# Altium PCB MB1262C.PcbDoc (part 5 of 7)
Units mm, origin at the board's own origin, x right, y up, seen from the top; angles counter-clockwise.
Board outline 208 x 250 mm, 6 copper layers (Top Layer, Layer 2, Layer 3, Layer 4, Layer 5, Bottom Layer), stack 1.596 mm thick; 483 components, 502 nets, 2134 pads, 1709 vias.
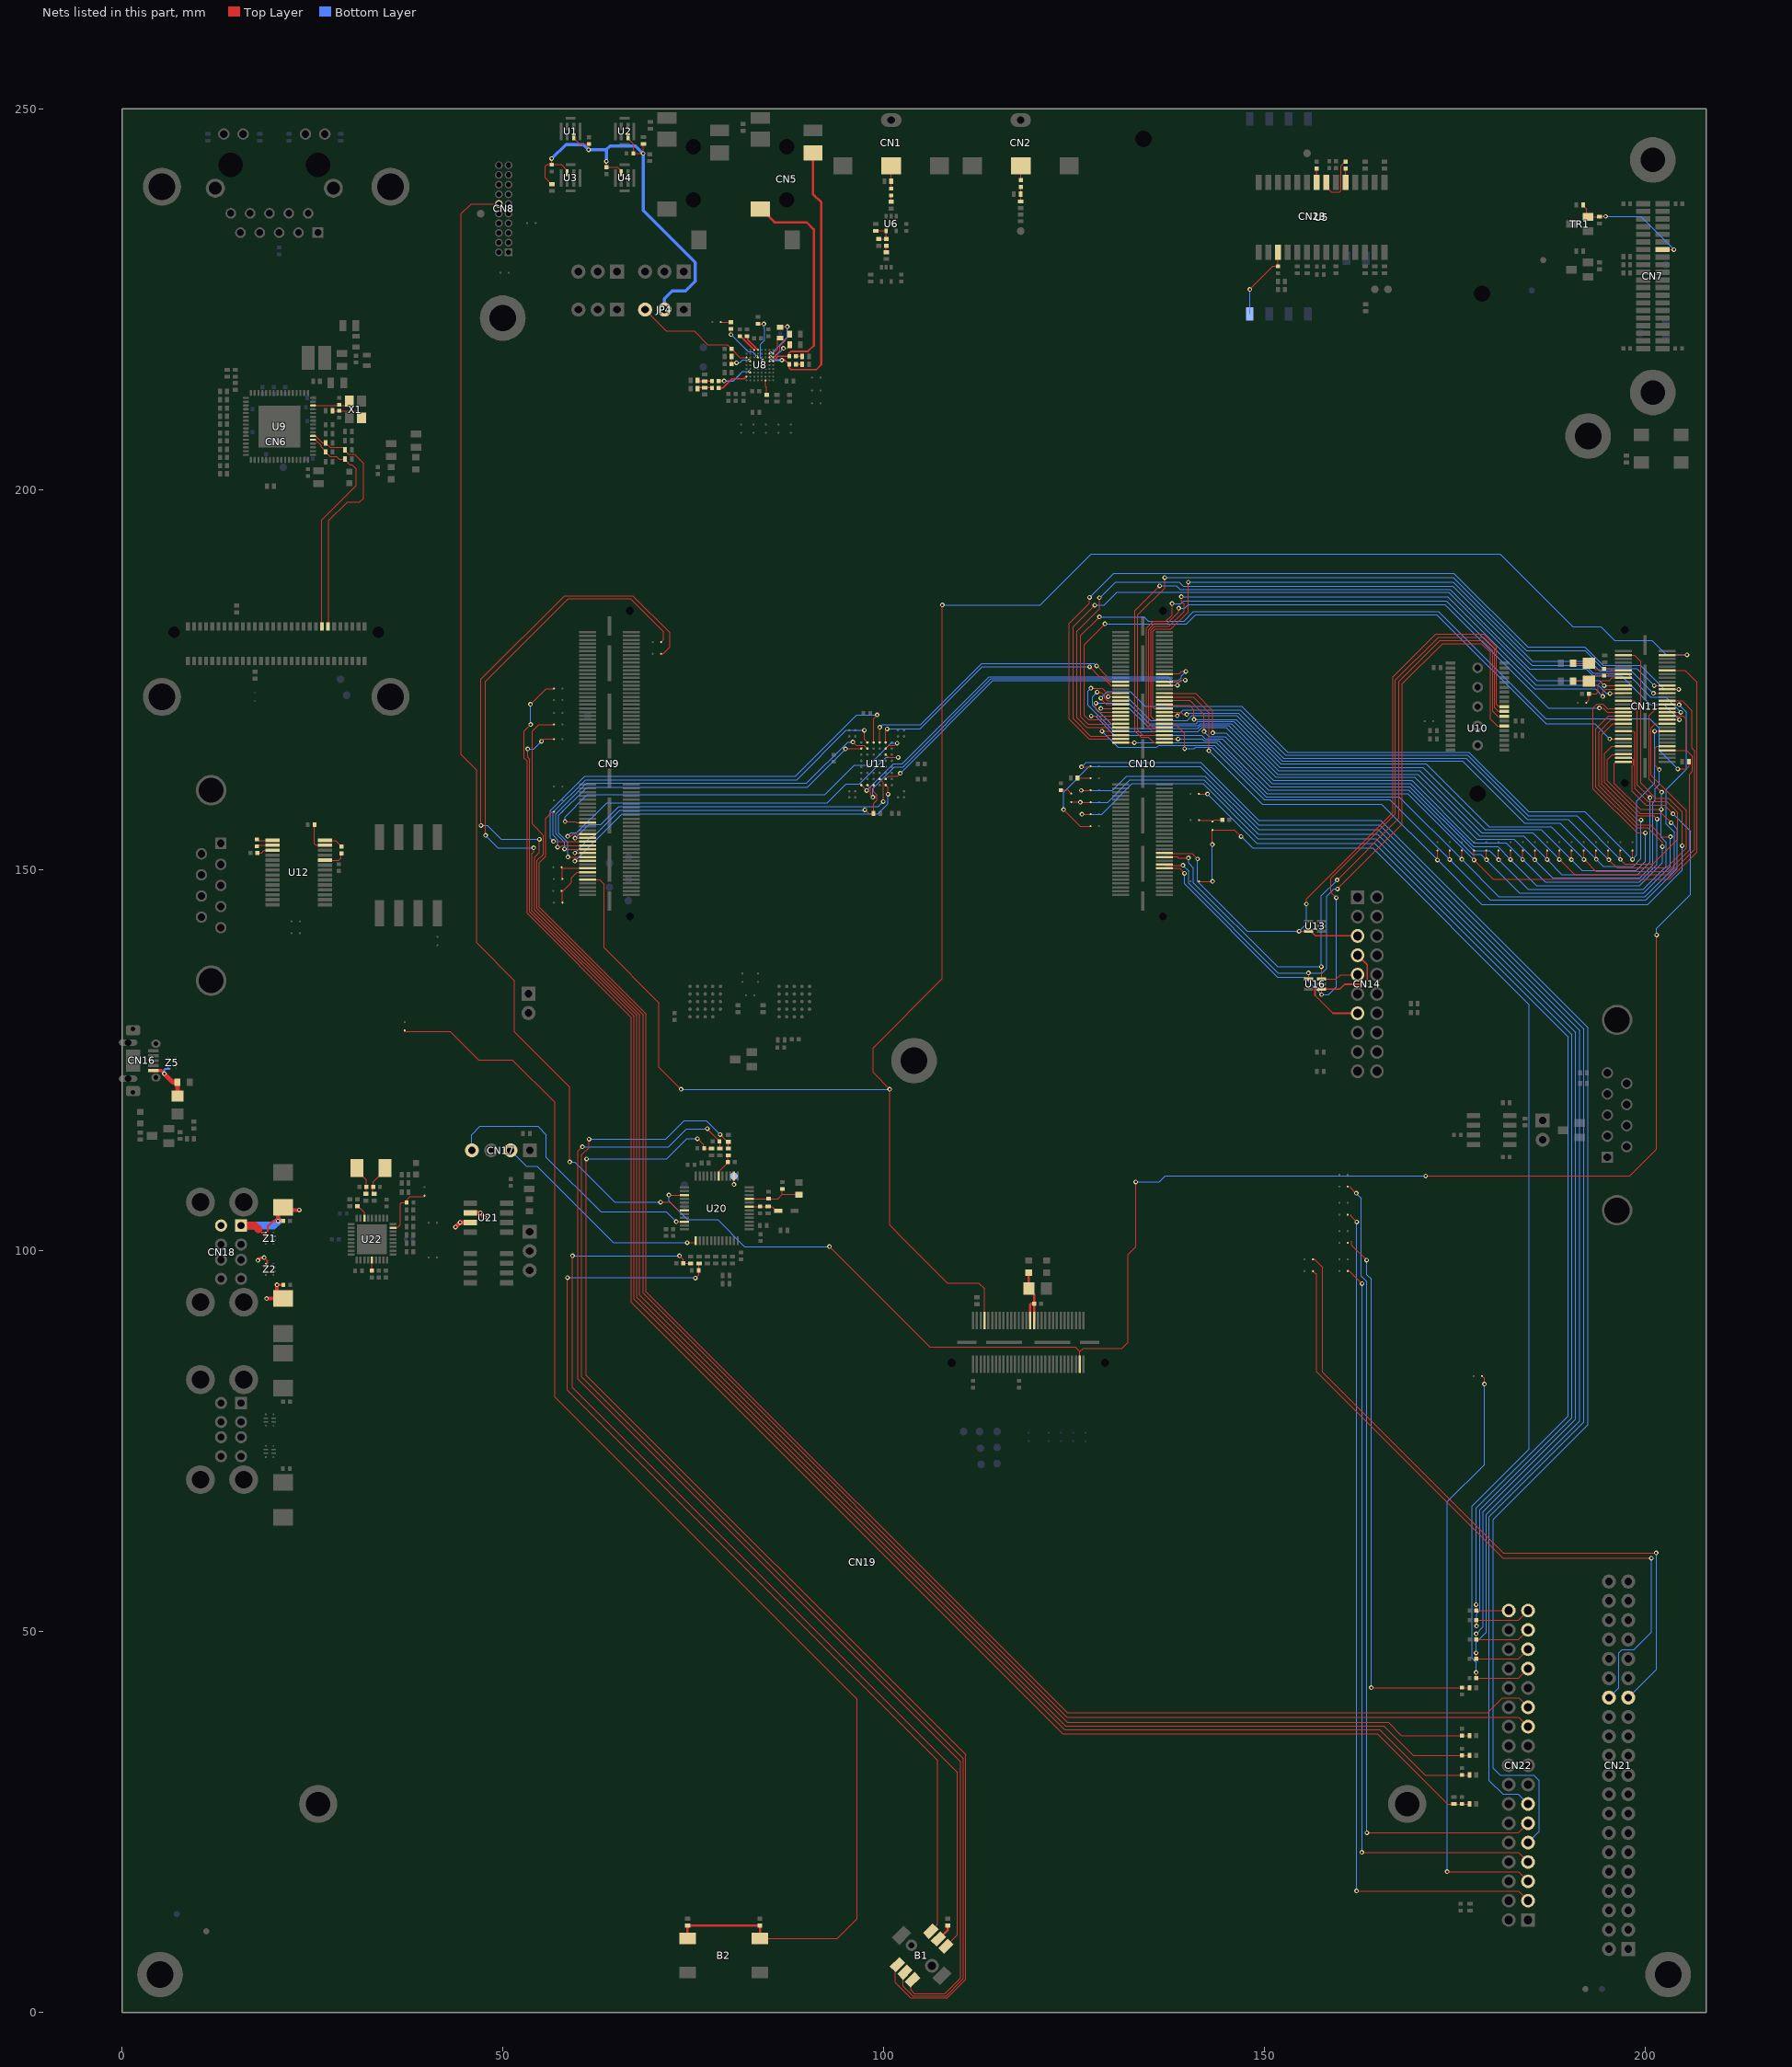
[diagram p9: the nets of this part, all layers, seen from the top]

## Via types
v1: diameter 0.6, hole 0.3, Top Layer to Bottom Layer, tented both sides, 979 vias
v2: diameter 0.55, hole 0.3, Top Layer to Bottom Layer, tented both sides, 687 vias
v3: diameter 0.3, hole 0.15, Top Layer to Bottom Layer, tented both sides, 31 vias
v4: diameter 0.4, hole 0.2, Top Layer to Bottom Layer, tented both sides, 12 vias

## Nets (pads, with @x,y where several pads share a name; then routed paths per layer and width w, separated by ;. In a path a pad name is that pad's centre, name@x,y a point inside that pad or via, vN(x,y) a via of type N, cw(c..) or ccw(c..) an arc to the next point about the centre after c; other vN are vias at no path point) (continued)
I2C2_SDA_C: CN7.14 R12.2 R14.1 TR1.2 | length 17.1
  Top Layer w0.1: R12.2@191.85,237.35 191.85,237.251 192.299,236.801 192.299,236.188 191.911,235.8 TR1.2@192.5,235.8 193.975,235.8 R14.1@194,235.825 194.033,235.792 194.098,235.857 194.109,235.846 v1(194.788,235.846) ; CN7.14@202.275,231.5 202.288,231.487 v1(203.773,231.487)
  Bottom Layer w0.1: v1@194.821,235.737 194.918,235.834 199.426,235.834 v1(203.773,231.487)
I2C5_SCL: CN9.105 SB51.1 SB52.2 | length 4.9
  Top Layer w0.1: SB51.1@57.717,150.392 57.86,150.25 ; SB52.2@57.817,148.842 57.817,150.208 57.86,150.25 ; CN9.105@61.13,150.25 57.86,150.25
I2C5_SDA: CN9.107 SB54.1 SB55.2 | length 6.2
  Top Layer w0.1: SB55.2@57.817,145.742 57.817,147.186 59.04,148.409 59.04,149.028 59.762,149.75 CN9.107@61.13,149.75
ID_SC: CN21.28 SB74.1 | length 89.2
  Top Layer w0.1: SB74.1@156.37,97.364 156.669,97.065 156.862,97.065 156.862,84.131 181.306,59.687 v1@200.81,59.687
  Bottom Layer w0.1: CN21.28@195.23,41.365 196.529,42.664 196.529,47.261 196.936,47.668 198.503,47.668 200.806,49.971 200.806,59.674 v1(200.81,59.678)
ID_SD: CN21.27 SB72.1 | length 89.6
  Top Layer w0.1: SB72.1@156.376,98.915 156.558,98.915 157.644,97.829 157.644,84.071 181.365,60.35 194.124,60.35 194.126,60.352 v1@201.45,60.352
  Bottom Layer w0.1: CN21.27@197.77,41.365 201.465,45.06 201.465,60.335 v1(201.45,60.35)
JTCK_SWCLK: CN10.100 CN14.9 U10.15 U16.3 | length 102.1
  Top Layer w0.13: CN10.100@136.87,151.75 136.875,151.745 136.893,151.764 138.538,151.764 138.694,151.608 140.019,151.608 v1(140.025,151.614) ; v1(157.462,137.338) 157.5,137.3 U16.3@157.5,135.7 159.394,135.7 159.971,136.277 CN14.9@162.3,136.277 ; v1(159.542,148.716) 167.655,156.829 167.655,174.772 173.069,180.187 178.62,180.187 179.965,178.842 179.965,170.89 180.625,170.23 U10.15@181.53,170.23 ; CN14.9@162.23,136.295 CN14.9@162.713,136.778
  Bottom Layer w0.13: v1(140.025,151.614) 140.047,151.614 140.047,150.916 140.675,150.288 140.675,148.354 151.691,137.338 v1(157.462,137.338) 157.462,146.636 v1(159.542,148.716)
JTDI: CN10.98 CN14.5 U10.19 U13.5 | length 95.5
  Top Layer w0.1: CN10.98@136.87,152.25 136.955,152.165 137.082,152.292 137.147,152.227 140.462,152.227 141.208,151.481 v1(141.217,151.481) ; v1(154.549,141.982) 154.567,142 U13.5@155.8,142 ; v1(155.505,145.563) 155.505,146.227 166.886,157.608 166.886,175.365 172.502,180.981 178.804,180.981 180.457,179.329 180.457,171.77 180.727,171.5 U10.19@181.53,171.5
  Top Layer w0.2: U13.5@155.8,142 156.086,142 156.711,141.375 CN14.5@162.23,141.375
  Bottom Layer w0.1: v1(141.217,151.481) 141.217,148.525 147.761,141.982 v1(154.549,141.982) 155.505,142.938 v1(155.505,145.563)
JTDO_TRACESWO: CN10.104 CN14.13 U10.11 U16.4 | length 105.5
  Top Layer w0.1: CN10.104@136.87,150.75 136.962,150.658 v1(139.284,150.658) ; v1(155.787,136.528) 155.8,136.515 U16.4@155.8,135.7 ; v1(159.595,147.53) 168.108,156.043 168.108,174.495 173.385,179.772 178.463,179.772 178.473,179.762 178.494,179.762 179.687,178.568 179.687,169.865 180.593,168.96 U10.11@181.53,168.96
  Top Layer w0.2: U16.4@155.8,135.7 156.154,135.7 156.643,135.211 156.643,133.569 158.997,131.215 CN14.13@162.23,131.215
  Bottom Layer w0.1: v1(139.284,150.658) 140.035,149.907 140.035,148.257 151.764,136.528 v1(155.787,136.528) 157.606,136.528 158.157,137.079 158.157,146.604 158.955,147.402 158.957,147.4 159.087,147.53 v1(159.595,147.53)
JTMS_SWDIO: CN10.106 CN14.7 U10.17 U16.1 | length 111
  Top Layer w0.1: CN10.106@136.87,150.25 138.85,150.25 v1(139.5,149.6) ; U16.1@157.5,134.4 157.5,133.675 v1(157.511,133.664) ; v1(159.445,146.377) 158.729,147.094 158.729,148.921 167.204,157.396 167.204,174.962 172.836,180.594 178.795,180.594 180.222,179.166 180.222,171.33 180.687,170.865 U10.17@181.53,170.865
  Top Layer w0.2: U16.1@157.5,134.4 159.906,134.4 160.521,135.014 162.923,135.014 163.489,135.58 163.489,137.576 CN14.7@162.23,138.835
  Bottom Layer w0.1: v1(139.5,149.6) 139.5,148.202 151.748,135.954 155.221,135.954 v1(157.511,133.664) 158.426,133.664 159.445,134.684 v1(159.445,146.377)
LCD_BL_CTRL: CN9.111 CN11.57 CN19.53 | length 275.8
  Top Layer w0.1: CN9.111@61.13,148.75 62.684,148.75 63.305,148.129 63.305,139.8 70.498,132.606 70.498,124.127 v1(73.399,121.226) ; v1(100.784,121.236) 100.784,103.394 102.734,101.444 ; v1@100.82,121.232 98.618,123.434 98.618,126.686 107.724,135.792 v1(107.724,184.822) ; 102.733,101.443 108.358,95.819 112.482,95.819 113.25,95.05 CN19.53@113.25,90.87 ; CN11.57@202.87,178.25 202.89,178.27 v1(205.478,178.27)
  Bottom Layer w0.1: v1(73.399,121.226) 100.773,121.226 v1(100.784,121.236) ; v1(107.724,184.822) 120.537,184.822 127.257,191.541 180.953,191.541 190.521,181.974 194.185,181.974 196.003,180.157 200.856,180.157 202.742,178.27 v1(205.478,178.27)
LCD_INT: CN11.4 CN19.4 U20.27 | length 224.7
  Top Layer w0.1: v1(71.8,107.336) 73.836,107.336 U20.27@73.85,107.35 ; v1(92.871,100.597) 106.087,87.382 108.082,87.382 ; 108.082,87.379 117.411,87.379 ; 117.411,87.379 125.14,87.379 125.75,86.769 ; CN19.4@125.75,85.13 125.75,86.769 ; 127.836,87.227 128.414,87.227 ; 128.131,87.225 126.206,87.225 125.75,86.769 ; 128.192,87.225 131.328,87.225 132.093,87.991 132.093,99.559 133.098,100.564 v1(133.098,109.06) ; v1(171.166,109.862) 197.99,109.862 201.497,113.369 v1(201.497,141.512) ; CN11.4@197.13,164.75 198.15,164.75 198.443,164.457 198.443,163.881 198.296,163.734 198.296,160.371 200.106,158.561 202.508,158.561 v1(203.646,157.422)
  Bottom Layer w0.1: v1(71.8,107.336) 71.8,106.562 74.252,104.111 78.233,104.111 81.747,100.597 v1(92.871,100.597) ; v1(133.098,109.06) 136.192,109.06 136.995,109.862 v1(171.166,109.862) ; v1(201.497,141.512) 201.497,142.341 201.745,142.59 205.97,146.816 205.97,155.099 v1(203.646,157.422)
LCD_RESET: C54.2 CN11.46 SB16.2 | length 7.3
  Top Layer w0.1: SB16.2@192.225,172 192.6,172.375 C54.2@192.6,173.175 193.575,173.175 193.825,173.425 193.825,174.375 194.375,174.925 195.325,174.925 195.65,175.25 CN11.46@197.13,175.25
LOOP: TP21.1 U20.14 | length 2.2
  Top Layer w0.1: v1(80.35,108.741) U20.14@80.35,109.85
  Bottom Layer w0.1: v1(80.35,108.741) TP21.1@80.35,109.825
LTDC_B0: CN10.57 CN11.39 | length 111.5
  Top Layer w0.13: v1(127.025,185.816) 127.025,185.046 124.368,182.389 124.368,169.831 126.949,167.25 129.232,167.25 129.233,167.251 CN10.57@131.13,167.25 CN10.57@131.13,167.25 ; CN11.39@202.87,173.75 v1(204.405,173.75)
  Bottom Layer w0.13: v1(127.025,185.816) 127.053,185.816 130.241,189.004 174.86,189.004 184.567,179.297 192.085,179.297 194.484,176.898 199.383,176.898 202.531,173.75 v1(204.405,173.75)
LTDC_B1: CN10.54 CN11.40 | length 86.4
  Top Layer w0.13: CN10.54@136.87,168.25 135.212,168.25 134.496,168.966 134.496,181.781 135.393,182.678 137.051,182.678 137.871,183.498 v1(137.871,185.017) ; v1(194.425,172.825) 194.425,173.425 194.75,173.75 CN11.40@197.13,173.75
  Bottom Layer w0.13: v1(137.871,185.017) 139.061,185.017 139.415,185.371 173.909,185.371 185.48,173.8 193.45,173.8 v1(194.425,172.825)
LTDC_B2: CN10.56 CN11.41 | length 97.1
  Top Layer w0.13: CN10.56@136.87,167.75 134.022,167.75 133.389,168.383 133.389,183.533 136.91,187.053 v1(136.91,188.423) ; v1(201.183,174.228) 202.848,174.228 CN11.41@202.87,174.25
  Bottom Layer w0.13: v1(136.91,188.423) 174.802,188.423 184.417,178.809 192.117,178.809 194.415,176.51 198.901,176.51 v1(201.183,174.228)
LTDC_B3: CN10.55 CN11.42 | length 98.5
  Top Layer w0.13: v1(127.717,184.801) 124.886,181.969 124.886,169.905 127.17,167.62 129.325,167.62 129.455,167.75 CN10.55@131.13,167.75 ; v1(194.615,174.235) 194.621,174.241 197.121,174.241 CN11.42@197.13,174.25
  Bottom Layer w0.13: v1(127.717,184.801) 128.969,184.801 130.65,186.482 174.178,186.482 185.776,174.883 193.966,174.883 v1(194.615,174.235)
LTDC_B4: CN10.51 CN11.27 | length 109.4
  Top Layer w0.13: v1(128.325,185.783) 128.325,184.333 125.394,181.403 125.394,170.005 126.65,168.75 CN10.51@131.13,168.75 ; CN11.27@202.87,170.75 202.896,170.724 v1(204.68,170.724)
  Bottom Layer w0.13: v1(128.325,185.783) 128.414,185.783 130.468,187.838 138.795,187.838 139.351,187.282 174.736,187.282 185.106,176.911 192.095,176.911 193.147,175.859 197.593,175.859 200.711,172.741 202.662,172.741 v1(204.68,170.724)
LTDC_B5: CN10.52 CN11.28 | length 84.4
  Top Layer w0.13: CN10.52@136.87,168.75 135.344,168.75 134.803,169.291 134.803,181.627 135.556,182.38 137.213,182.38 138.746,183.912 v1(138.746,184.397) ; v1(193.973,171.307) 194.466,171.307 195.006,170.767 197.113,170.767 CN11.28@197.13,170.75
  Bottom Layer w0.13: v1(138.746,184.397) 139.544,184.397 140.027,184.88 173.716,184.88 187.289,171.307 v1(193.973,171.307)
LTDC_B6: CN10.53 CN11.31 SB49.1 | length 114.4
  Top Layer w0.13: v1(128.675,168.25) CN10.53@131.13,168.25 ; v1(175.91,151.432) 175.926,151.448 SB49.1@175.926,152.592 ; CN11.31@202.87,171.75 202.901,171.719 v1(204.45,171.719)
  Bottom Layer w0.13: v1(128.675,168.25) 130.785,166.14 135.855,166.14 136.128,166.413 143.453,166.413 150.208,159.658 167.684,159.658 v1(175.91,151.432) 180.79,146.552 199.956,146.552 203.821,150.417 203.821,154.999 202.762,156.058 202.762,160.576 205.412,163.226 205.412,170.757 v1(204.45,171.719)
LTDC_B7: CN10.50 CN11.6 SB35.1 | length 103.4
  Top Layer w0.13: CN10.50@136.87,169.25 138.251,169.25 139.521,167.98 v1(139.521,165.948) ; v1(174.326,151.401) SB35.1@174.326,152.592 ; CN11.6@197.13,165.25 197.095,165.215 195.715,165.215 195.032,164.532 195.032,161.727 199.299,157.46 202.171,157.46 v1(203.409,156.222)
  Bottom Layer w0.13: v1(139.521,165.948) 140.797,165.948 140.997,166.148 143.112,166.148 149.971,159.29 166.437,159.29 v1(174.326,151.401) 179.636,146.091 200.095,146.091 204.221,150.217 204.221,155.409 v1(203.409,156.222)
LTDC_CLK: CN10.36 CN11.58 SB38.1 | length 118.6
  Top Layer w0.13: CN10.36@136.87,172.75 136.881,172.761 140.65,172.761 142.712,170.7 142.704,170.692 v1(142.704,165.683) ; v1(172.727,151.33) SB38.1@172.726,152.592 ; CN11.58@197.13,178.25 197.165,178.215 198.588,178.215 199.427,177.377 199.427,161.42 201.374,159.473 203.026,159.473 204.837,157.662 v1(204.837,153.206)
  Bottom Layer w0.13: v1(142.704,165.683) 149.703,158.684 165.373,158.684 v1(172.727,151.33) 178.537,145.52 200.342,145.52 204.837,150.014 v1(204.837,153.206)
LTDC_DE: CN10.49 R82.2 | length 108.9
  Top Layer w0.13: v1(128.34,183.268) 125.875,180.803 125.875,170.162 126.844,169.193 131.073,169.193 CN10.49@131.13,169.25 ; v1(204.289,163.304) 205.381,163.304 205.75,163.673 R82.2@205.75,164.25
  Bottom Layer w0.13: v1(128.34,183.268) 128.346,183.274 134.198,183.274 134.749,182.723 139.454,182.723 140.68,183.949 172.862,183.949 186.936,169.875 200.599,169.875 201.852,168.622 201.852,165.741 v1(204.289,163.304)
LTDC_G0: CN10.43 CN11.30 SB45.1 | length 115.5
  Top Layer w0.13: v1(127.893,171.945) 127.893,171.094 128.238,170.75 CN10.43@131.13,170.75 ; v1(190.293,151.389) 190.326,151.422 SB45.1@190.326,152.592 ; CN11.30@197.13,171.25 195.003,171.25 194.396,171.857 193.674,171.857 193.16,171.343 193.16,160.674 198.941,154.894 v1(200.029,154.894)
  Bottom Layer w0.13: v1(127.893,171.945) 132.18,171.945 134.893,169.232 141.013,169.232 141.302,169.52 145.996,169.52 152.005,163.511 170.797,163.511 178.973,155.335 186.347,155.335 v1(190.293,151.389) 191.716,149.966 198.828,149.966 200.029,151.167 v1(200.029,154.894)
LTDC_G1: CN10.41 CN11.33 SB44.1 | length 114.6
  Top Layer w0.13: v1(128.506,171.246) 128.51,171.25 CN10.41@131.13,171.25 ; SB44.1@188.726,152.592 188.726,151.405 v1(188.73,151.402) 190.714,149.417 203.163,149.417 206.494,152.748 206.494,165.681 206.134,166.041 206.134,170.955 204.839,172.25 CN11.33@202.87,172.25 CN11.33@202.857,172.263
  Bottom Layer w0.13: v1(128.506,171.246) 132.301,171.246 134.559,168.988 141.304,168.988 141.58,169.264 145.682,169.264 151.868,163.078 170.372,163.078 178.543,154.908 185.224,154.908 v1(188.73,151.402)
LTDC_G2: CN10.37 CN11.34 SB50.1 | length 112.7
  Top Layer w0.13: v1(128.031,173.396) 128.031,173.369 128.583,173.369 129.024,172.928 129.024,172.591 129.366,172.25 CN10.37@130.074,172.25 ; v1(187.119,151.405) 187.126,151.412 SB50.1@187.126,152.592 ; CN11.34@197.13,172.25 198.454,172.25 198.959,171.746 198.959,161.195 v1(200.624,159.53)
  Bottom Layer w0.13: v1(128.031,173.396) 127.428,172.793 127.428,171.65 130.471,168.607 141.248,168.607 141.627,168.986 145.325,168.986 151.711,162.601 170.12,162.601 178.242,154.479 184.045,154.479 v1(187.119,151.405) 189.068,149.456 199.016,149.456 200.633,151.073 200.633,159.521 v1(200.624,159.53)
LTDC_G3: CN10.42 CN11.37 | length 90
  Top Layer w0.13: CN10.42@136.87,171.25 135.565,171.25 135.376,171.438 135.376,181.385 135.651,181.66 137.729,181.66 140.003,183.934 v1(140.003,187.815) ; v1(201.084,173.246) 202.866,173.246 CN11.37@202.87,173.25
  Bottom Layer w0.13: v1(140.003,187.815) 174.811,187.815 185.179,177.447 192.687,177.447 193.97,176.164 198.166,176.164 v1(201.084,173.246)
LTDC_G4: CN10.48 CN11.38 | length 84.7
  Top Layer w0.13: CN10.48@137.445,169.764 137.431,169.75 CN10.48@136.87,169.75 135.55,169.75 135.104,170.196 135.104,181.526 135.618,182.04 137.491,182.04 139.443,183.992 139.443,184.915 139.072,185.286 v1(139.072,185.926) ; v1(195.366,173.21) 195.406,173.25 CN11.38@197.13,173.25
  Bottom Layer w0.13: v1(139.072,185.926) 139.084,185.915 174.056,185.915 185.666,174.304 193.795,174.304 194.889,173.21 v1(195.366,173.21)
LTDC_G5: CN10.60 CN11.23 | length 102.2
  Top Layer w0.13: v1(136.25,187.349) 133.017,184.116 133.017,168.253 133.806,167.464 134.769,167.464 135.483,166.75 CN10.60@136.87,166.75 ; CN11.23@202.87,169.75 202.955,169.665 203.085,169.796 203.112,169.768 v1(204.495,169.768)
  Bottom Layer w0.13: v1(136.25,187.349) 138.435,187.349 138.897,186.887 174.338,186.887 184.802,176.422 192.259,176.422 193.163,175.519 196.898,175.519 200.632,171.785 202.478,171.785 v1(204.495,169.768)
LTDC_G6: CN10.58 CN11.24 SB40.1 | length 104.6
  Top Layer w0.13: CN10.58@136.87,167.25 136.897,167.223 v1(138.655,167.223) ; SB40.1@179.126,152.592 179.158,152.56 v1(179.158,151.375) v1@179.158,151.318 ; CN11.24@197.13,169.75 195.526,169.75 193.913,168.138 193.913,161.095 199.087,155.921 200.688,155.921 202.223,154.387 v1(203.307,154.387)
  Bottom Layer w0.13: v1(138.655,167.223) 141.845,167.223 142.066,167.002 144.008,167.002 145.863,165.147 147.149,163.861 150.488,160.522 168.924,160.522 177.346,152.1 178.391,152.1 179.116,151.375 v1(179.158,151.375) 179.158,151.333 183.496,146.995 199.811,146.995 203.307,150.49 v1(203.307,154.387)
LTDC_G7: CN10.59 CN11.49 SB39.1 | length 113.2
  Top Layer w0.13: CN10.59@131.13,166.75 131.147,166.733 v1(132.919,166.733) ; SB39.1@177.526,152.592 177.526,151.364 v1(177.535,151.355) 180.046,148.845 203.202,148.845 206.769,152.412 206.769,174.699 205.218,176.25 CN11.49@202.87,176.25 CN11.49@202.786,176.25 ; CN11.49@202.77,176.27 CN11.49@202.786,176.287
  Bottom Layer w0.13: v1(132.919,166.733) 132.682,166.733 132.675,166.74 143.675,166.74 150.337,160.078 168.813,160.078 v1(177.535,151.355)
LTDC_HSYNC: CN10.33 CN11.9 SB43.1 | length 110
  Top Layer w0.13: v1(127.226,173.887) 128.687,173.887 129.324,173.25 CN10.33@131.13,173.25 ; v1(185.497,151.362) 185.526,151.391 SB43.1@185.526,152.592 ; v1(201.847,163.217) 201.321,163.743 201.321,166.02 201.551,166.25 CN11.9@202.87,166.25
  Bottom Layer w0.13: v1(127.226,173.887) 126.836,173.498 126.836,171.636 130.279,168.193 141.273,168.193 141.805,168.725 144.97,168.725 151.47,162.225 169.712,162.225 177.87,154.068 182.792,154.068 v1(185.497,151.362) 187.865,148.995 199.285,148.995 200.994,150.704 200.994,158.859 201.319,159.183 201.319,160.712 201.847,161.241 v1(201.847,163.217)
LTDC_R0: CN10.47 CN11.14 | length 93.5
  Top Layer w0.13: v1(129.064,182.352) 126.337,179.625 126.337,170.332 126.919,169.75 CN10.47@131.13,169.75 ; v1(195.338,167.242) 197.122,167.242 CN11.14@197.13,167.25
  Bottom Layer w0.13: v1(129.064,182.352) 139.777,182.352 140.242,182.817 140.979,183.554 172.617,183.554 186.962,169.209 193.371,169.209 v1(195.338,167.242)
LTDC_R1: CN10.39 CN11.17 SB34.1 | length 103.1
  Top Layer w0.13: v1@128.558,172.466 129.274,171.75 CN10.39@131.13,171.75 ; SB34.1@198.326,152.592 198.326,151.417 v1(198.328,151.415) ; v1(201.238,168.25) CN11.17@202.87,168.25 202.897,168.277 202.875,168.3 CN11.17@202.847,168.273
  Bottom Layer w0.13: v1(128.509,172.602) 129.355,173.448 132.381,173.448 134.327,171.501 147.017,171.501 153.027,165.491 176.856,165.491 184.674,157.674 192.07,157.674 v1(198.328,151.415) 198.912,151.999 198.912,159.097 201.238,161.423 v1(201.238,168.25)
LTDC_R2: CN10.46 CN11.18 SB37.1 | length 98.1
  Top Layer w0.13: CN10.46@136.773,170.266 136.781,170.274 138.22,170.274 v1(138.554,170.274) ; CN10.46@136.87,170.25 CN10.46@136.891,170.271 ; SB37.1@196.726,152.592 196.726,151.435 v1(196.742,151.418) 197.319,150.841 201.026,150.841 204.266,154.081 204.266,157.551 202.814,159.004 200.355,159.004 198.665,160.694 198.665,168.017 198.432,168.25 CN11.18@197.13,168.25
  Bottom Layer w0.13: v1(138.554,170.274) 139.33,171.05 146.851,171.05 152.771,165.13 176.636,165.13 184.639,157.127 191.034,157.127 v1(196.742,151.418)
LTDC_R3: CN10.44 CN11.21 SB48.1 | length 99.5
  Top Layer w0.13: CN10.44@136.87,170.75 139.028,170.75 139.314,170.464 v1(139.81,170.464) ; SB48.1@195.126,152.592 195.126,151.467 v1(195.223,151.37) 196.268,150.324 202.814,150.324 205.419,152.93 205.419,157.845 200.773,162.491 200.773,168.706 201.317,169.25 CN11.21@202.87,169.25
  Bottom Layer w0.13: v1(139.81,170.464) 139.999,170.653 146.591,170.653 152.512,164.733 176.484,164.733 184.521,156.696 189.897,156.696 v1(195.223,151.37)
LTDC_R4: CN10.35 CN11.22 SB47.1 | length 105.1
  Top Layer w0.13: v1(129.489,172.784) 131.054,172.784 131.067,172.771 131.088,172.792 CN10.35@131.13,172.75 ; SB47.1@193.526,152.592 193.526,151.487 v1(193.572,151.441) ; CN11.22@197.13,169.25 195.776,169.25 194.299,167.773 194.299,161.275 198.975,156.599 v1(199.452,156.599)
  Bottom Layer w0.13: v1(129.489,172.784) 131.937,172.784 135.043,169.678 139.864,169.678 140.506,170.32 146.345,170.32 152.309,164.357 175.987,164.357 184.159,156.184 188.829,156.184 v1(193.572,151.441) 194.473,150.54 198.471,150.54 199.452,151.521 v1(199.452,156.599)
LTDC_R5: CN10.40 CN11.7 CN11.25 SB46.1 | length 104.1
  Top Layer w0.13: CN10.40@136.87,171.75 136.958,171.662 140.173,171.662 140.759,171.076 v1(140.759,169.783) ; SB46.1@191.926,152.592 191.926,151.424 v1(191.955,151.395) 191.982,151.395 193.521,149.856 202.982,149.856 205.828,152.702 205.828,162.604 206.218,162.994 206.218,164.945 205.414,165.75 ; CN11.25@202.806,170.314 CN11.25@202.87,170.25 204.963,170.25 205.414,169.799 205.414,165.75 ; CN11.7@202.87,165.75 205.414,165.75
  Bottom Layer w0.13: v1(140.759,169.783) 146.291,169.783 152.115,163.959 171.248,163.959 179.511,155.695 187.655,155.695 v1(191.955,151.395)
LTDC_R6: CN10.38 CN11.26 SB36.1 | length 105.6
  Top Layer w0.13: CN10.38@136.87,172.25 136.916,172.296 140.21,172.296 142.062,170.445 v1(142.062,168.222) ; v1(182.309,151.393) 182.326,151.41 SB36.1@182.326,152.592 ; CN11.26@197.13,170.25 197.114,170.234 195.176,170.234 193.512,168.57 193.512,160.921 198.864,155.568 200.351,155.568 202.266,153.652 v1(202.266,153.084)
  Bottom Layer w0.13: v1(142.062,168.222) 142.729,167.555 144.823,167.555 150.996,161.381 169.16,161.381 177.461,153.08 180.622,153.08 v1(182.309,151.393) 185.736,147.966 199.248,147.966 202.266,150.985 v1(202.266,153.084)
LTDC_R7: CN10.45 CN11.2 CN11.29 SB41.1 | length 126.3
  Top Layer w0.13: v1(127.261,170.25) CN10.45@131.13,170.25 ; SB41.1@180.726,152.592 180.726,151.4 v1(180.743,151.384) ; CN11.2@197.13,164.25 196.172,164.25 195.95,164.028 195.95,161.375 199.341,157.983 v1(202.109,157.983) ; v1(202.15,160.245) 200.489,161.907 200.489,170.34 201.396,171.247 202.867,171.247 CN11.29@202.87,171.25
  Bottom Layer w0.13: v1(127.261,170.25) 127.777,170.25 130.281,167.747 141.757,167.747 142.235,167.268 144.446,167.268 150.747,160.966 169.069,160.966 177.481,152.555 179.571,152.555 v1(180.743,151.384) 184.632,147.495 199.725,147.495 202.731,150.501 202.731,153.668 202.109,154.291 v1(202.109,157.983) 202.15,158.024 v1(202.15,160.245)
LTDC_VSYNC: CN10.34 CN11.10 SB42.1 | length 100.2
  Top Layer w0.13: CN10.34@136.87,173.25 136.91,173.21 140.957,173.21 143.229,170.937 v1(143.229,168.04) ; v1(183.908,151.415) 183.926,151.433 SB42.1@183.926,152.592 ; CN11.10@197.13,166.25 195.636,166.25 194.673,165.287 194.673,161.498 199.046,157.126 201.138,157.126 v1(201.553,156.711)
  Bottom Layer w0.13: v1(143.229,168.04) 144.953,168.04 151.197,161.796 169.338,161.796 177.538,153.596 181.727,153.596 v1(183.908,151.415) 186.84,148.483 199.252,148.483 201.553,150.783 v1(201.553,156.711)
MC_BUSVOLTAGE: C117.2 R135.2 R136.2 SB14.1 | length 226
  Top Layer w0.1: v1(53.627,171.776) 55.693,173.842 SB14.1@56.717,173.842 ; v1(53.664,169.12) 52.823,168.279 52.823,164.712 53.193,164.342 53.193,144.343 66.87,130.666 66.87,93.277 123.515,36.633 164.8,36.633 174.039,27.394 R135.2@174.873,27.394 C117.2@175.927,27.394 R136.2@176.918,27.394
  Bottom Layer w0.1: v1(53.627,171.776) 53.627,169.157 v1(53.664,169.12)
MC_CURRENTA: C116.2 R134.1 SB20.1 | length 217.6
  Top Layer w0.1: v1(53.273,165.922) 53.273,164.82 53.504,164.589 53.504,144.529 67.225,130.807 67.225,93.655 123.732,37.148 165.144,37.148 171.091,31.201 C116.2@175.927,31.201 R134.1@176.918,31.201 ; v1(55.081,166.927) 55.38,167.225 SB20.1@56.717,167.225
  Bottom Layer w0.1: v1(53.273,165.922) 54.077,165.922 v1(55.081,166.927)
MC_CURRENTB: C115.2 R133.1 SB12.1 | length 257.5
  Top Layer w0.1: v1(47.731,154.584) 47.731,174.801 58.607,185.677 66.757,185.677 71.124,181.31 71.124,180.281 SB12.1@70.793,179.951 ; v1(54.05,152.95) 54.05,152.397 53.853,152.2 53.853,144.683 67.603,130.933 67.603,93.921 123.877,37.647 165.681,37.647 169.563,33.765 C115.2@175.927,33.765 R133.1@176.918,33.765
  Bottom Layer w0.1: v1(47.731,154.584) 49.366,152.95 v1(54.05,152.95)
MC_CURRENTC: C114.2 R132.1 SB13.1 | length 261
  Top Layer w0.1: v1(47.14,155.881) 47.14,175.091 58.101,186.051 67.06,186.051 71.916,181.195 71.916,179.296 71.033,178.413 SB13.1@70.793,178.413 ; v1(54.797,154.053) 54.797,152.342 54.169,151.714 54.169,144.802 67.982,130.989 67.982,94.23 124.102,38.111 166.263,38.111 167.994,36.38 C114.2@175.927,36.38 R132.1@176.918,36.38
  Bottom Layer w0.1: v1(47.14,155.881) 47.978,155.881 49.806,154.053 v1(54.797,154.053)
MC_DISSIPATIVEBRAKE: CN22.23 SB29.1 | length 209.8
  Top Layer w0.1: SB29.1@56.717,157.692 56.512,157.692 55.639,156.819 55.639,151.849 54.784,150.994 54.784,145.126 68.803,131.107 68.803,94.668 124.102,39.37 179.307,39.37 181.244,41.307 183.408,41.307 CN22.23@184.62,40.095
MC_EMERGENCYSTOP: R83.1 SB22.1 | length 1.7
  Top Layer w0.13: R83.1@125.459,162.096 127.179,162.096 SB22.1@127.183,162.093
MC_ENA: C110.2 CN22.31 SB25.2 SB28.1 | length 175.1
  Top Layer w0.13: SB25.2@124.615,158.961 125.789,158.961 v1(125.818,158.932) SB28.1@127.182,158.932 ; v1(177.794,49.747) 177.794,48.999 C110.2@177.818,48.975 ; C110.2@177.842,48.951 C110.2@177.818,48.975 ; CN22.31@184.62,50.245 183.35,48.975 C110.2@177.818,48.975
  Bottom Layer w0.13: v1(125.818,158.932) 129.424,158.932 132.349,161.857 142.064,161.857 149.174,154.747 164.839,154.747 190.875,128.711 190.875,77.931 178.727,65.783 178.727,50.68 v1(177.794,49.747)
MC_ENB: C109.2 CN22.33 SB30.1 | length 171.7
  Top Layer w0.13: v1(126.045,157.344) 127.174,157.344 SB30.1@127.183,157.354 ; v1(177.842,50.753) 177.842,51.501 C109.2@177.818,51.525 183.35,51.525 CN22.33@184.62,52.795
  Bottom Layer w0.13: v1(126.045,157.344) 128.646,157.344 132.657,161.355 141.916,161.355 149.149,154.123 164.642,154.123 190.384,128.381 190.384,78.114 178.318,66.048 178.318,52.824 177.842,52.348 v1(177.842,50.753)
MC_ENINDEX: C108.1 CN22.34 SB26.1 | length 146.3
  Top Layer w0.13: SB26.1@141.393,160.026 141.398,160.021 v1(142.525,160.021) ; v1(177.794,53.572) 177.794,52.824 C108.1@177.818,52.8 177.823,52.795 CN22.34@182.08,52.795
  Bottom Layer w0.13: v1(142.525,160.021) 144.774,157.772 149.005,153.541 164.44,153.541 189.872,128.109 189.872,78.322 177.794,66.244 v1(177.794,53.572)
MC_HEATSINK: C113.2 R131.2 SB70.1 | length 72.6
  Top Layer w0.1: 161.46,101.29 161.46,100.773 v1(163.433,98.8) ; v1(164.025,42.675) 164.029,42.671 C113.2@175.927,42.671 175.954,42.644 R131.2@176.918,42.644
  Bottom Layer w0.1: v1(163.433,98.8) 163.433,96.901 164.012,96.321 v1@164.012,42.675
MC_NTC: CN22.21 SB19.1 | length 223.5
  Top Layer w0.1: SB19.1@56.717,169.129 54.754,169.129 53.869,168.244 53.869,156.039 55.329,154.578 55.329,152.112 54.488,151.271 54.488,144.938 68.413,131.013 68.413,94.456 124.088,38.781 183.394,38.781 CN22.21@184.62,37.555
MC_PFCPWM: C111.2 CN22.29 SB24.1 | length 176.8
  Top Layer w0.13: v1(125.955,160.477) 127.147,160.477 SB24.1@127.183,160.513 ; v1(177.794,47.222) 177.794,46.474 C111.2@177.818,46.45 ; C111.2@177.842,46.426 C111.2@177.818,46.45 ; CN22.29@184.62,47.72 183.35,46.45 C111.2@177.818,46.45
  Bottom Layer w0.13: v1(125.955,160.477) 130.01,160.477 131.901,162.368 142.208,162.368 149.219,155.357 164.957,155.357 191.387,128.927 191.387,77.659 179.154,65.426 179.154,49.965 177.794,48.605 v1(177.794,47.222)
MC_PFCSYNC1: C60.2 SB31.1 SB32.1 | length 3.3
  Top Layer w0.13: SB32.1@141.403,156.582 142.99,156.582 SB31.1@143.186,156.387 143.419,156.62 C60.2@144.475,156.62
MC_PFCSYNC2: C112.2 CN22.27 SB31.2 SB53.1 | length 158.8
  Top Layer w0.13: SB53.1@141.403,148.561 141.41,148.568 141.447,148.531 v1(143.189,148.531) ; v1(143.165,153.373) 143.165,155.266 SB31.2@143.186,155.287 146.066,155.287 v1(146.943,154.41) ; v1(177.794,44.672) 177.794,43.924 C112.2@177.818,43.9 ; C112.2@177.842,43.876 C112.2@177.818,43.9 ; CN22.27@184.62,45.17 183.35,43.9 C112.2@177.818,43.9
  Bottom Layer w0.13: v1(143.165,153.373) 143.165,148.555 v1(143.189,148.531) ; v1(146.943,154.41) 148.443,152.909 164.194,152.909 184.748,132.355 184.748,73.984 177.242,66.478 177.242,46.534 177.794,45.981 v1(177.794,44.672)
MC_UH: CN22.3 SB67.1 | length 112.2
  Top Layer w0.1: 161.363,104.801 161.363,104.569 v1(162.11,103.822) ; v1(162.101,15.976) 183.339,15.976 CN22.3@184.62,14.695 CN22.3@184.625,14.7
  Bottom Layer w0.1: v1@162.11,15.976 v1(162.11,103.822)
MC_UL: CN22.5 SB76.1 | length 78.4
  Top Layer w0.1: v1(174,18.52) 174.013,18.507 183.348,18.507 CN22.5@184.62,17.235 ; SB76.1@178.565,83.591 178.868,83.288 v1(178.868,82.522)
  Bottom Layer w0.1: v1@173.992,18.52 173.992,67.096 178.868,71.972 v1(178.868,82.522)
MC_VH: CN22.7 SB75.1 | length 99.7
  Top Layer w0.1: SB75.1@160.936,97.364 161.037,97.465 162.774,95.728 v1(162.804,95.728) ; v1(162.8,21.05) 162.802,21.052 183.343,21.052 CN22.7@184.62,19.775
  Bottom Layer w0.1: v1@162.804,21.05 v1(162.804,95.728)
MC_VL: CN22.9 SB21.1 | length 200.2
  Top Layer w0.13: v1(125.985,163.582) 127.093,163.582 SB21.1@127.183,163.672
  Bottom Layer w0.13: v1(125.985,163.582) 126.575,164.172 141.645,164.172 149.272,156.545 165.239,156.545 192.463,129.321 192.463,77.18 180.056,64.774 180.056,32.088 180.949,31.196 185.373,31.196 186.087,30.483 186.087,23.782 CN22.9@184.62,22.315
MC_WH: CN22.11 SB65.1 | length 107.5
  Top Layer w0.1: 161.242,108.457 161.242,108.358 162.001,107.599 v1(162.05,107.599) ; v1(163.45,23.625) 163.454,23.629 183.394,23.629 CN22.11@184.62,24.855 CN22.11@184.64,24.875
  Bottom Layer w0.1: v1(162.05,107.599) 162.721,106.929 162.721,96.724 163.44,96.005 v1@163.44,23.625
MC_WL: CN22.13 SB33.1 | length 200.9
  Top Layer w0.13: v1(123.617,157.962) 125.805,155.774 SB33.1@127.183,155.774
  Bottom Layer w0.13: v1(123.617,157.962) 123.617,160.263 126.962,163.607 141.592,163.607 149.257,155.942 165.106,155.942 191.943,129.105 191.943,77.545 179.525,65.128 179.525,30.451 181.296,28.681 183.334,28.681 CN22.13@184.62,27.395
MDC: CN6.46 R66.1 R69.2 U9.53 | length 30
  Top Layer w0.1: U9.53@25.075,206.525 25.39,206.525 26.147,205.767 26.147,205.571 26.737,204.981 R66.1@26.737,204.925 27.312,204.35 28.172,204.35 28.54,203.981 R69.2@29.287,203.981 29.287,203.872 29.935,203.224 30.228,203.224 30.734,202.718 30.734,200.502 26.25,196.018 CN6.46@26.25,182
MDIO: CN6.48 R63.1 R65.2 U9.54 | length 32.6
  Top Layer w0.1: U9.54@25.075,207.025 25.075,206.966 25.133,207.024 25.355,207.024 26.264,206.116 R63.1@26.737,206.116 27.318,205.534 29.007,205.534 29.287,205.254 29.287,205.071 29.738,204.621 30.508,204.621 31.694,203.435 31.694,198.855 31.183,198.344 29.586,198.344 27.153,195.91 27.153,195.138 ; CN6.48@27.05,182 27.153,182.103 27.153,195.138
MFX_SWCLK: CN17.2 U20.37 | length 29.6
  Top Layer w0.13: v1(74.206,101.098) 75.35,101.098 U20.37@75.35,101.35
  Bottom Layer w0.13: CN17.2@51.02,113.219 53.115,111.124 54.496,111.124 64.523,101.098 v1(74.206,101.098)
MFX_SWDIO: CN17.4 U20.34 | length 37.3
  Top Layer w0.1: v1(72.76,103.85) U20.34@73.85,103.85
  Bottom Layer w0.1: CN17.4@45.927,113.288 45.927,115.271 47.022,116.366 54.622,116.366 55.717,115.271 55.717,112.314 62.901,105.13 71.479,105.13 v1(72.76,103.85)
MIC_MEMS_LED: CN8.12 U20.31 | length 153.5
  Top Layer w0.1: CN8.12@49.482,237.486 45.834,237.486 44.553,236.204 44.553,181.83 44.553,165.161 46.553,163.161 46.553,140.476 51.541,135.487 51.541,128.762 58.755,121.548 58.75,121.542 58.75,116.809 58.751,116.808 v1@58.751,111.761 ; v1(70.71,106.398) 71.965,106.398 73.013,105.35 U20.31@73.85,105.35
  Bottom Layer w0.1: v1@58.769,111.709 59.414,111.709 64.724,106.398 v1(70.71,106.398)
  other v1: 58.804,111.709
NAND_ALE: CN9.101 U11.C4 | length 48.5
  Top Layer w0.1: v1(59.47,151.206) 59.514,151.25 CN9.101@61.13,151.25 ; U11.C4@100.275,161.175 100.575,160.875 v1(100.575,159.969)
  Bottom Layer w0.1: v1(59.47,151.206) 65.667,157.403 99.235,157.403 100.575,158.743 v1(100.575,159.969)
NAND_CLE: CN9.89 U11.D5 | length 47.3
  Top Layer w0.1: v1(59.476,154.211) 59.514,154.25 CN9.89@61.13,154.25 ; U11.D5@99.475,161.975 99.961,161.489 v1(99.961,159.001)
  Bottom Layer w0.1: v1(59.476,154.211) 61.29,156.026 62.913,156.026 65.251,158.364 99.324,158.364 v1(99.961,159.001)
NAND_D0: CN9.87 U11.H4 | length 52.2
  Top Layer w0.1: v1(58.506,154.466) 58.927,154.466 59.211,154.75 CN9.87@61.13,154.75 ; U11.H4@100.275,165.175 100.65,164.8 v1(101.9,164.8)
  Bottom Layer w0.1: v1(58.506,154.466) 58.976,154.935 59.71,154.935 63.649,158.874 92.618,158.874 95.061,161.317 96.831,161.317 100.314,164.8 v1(101.9,164.8)
NAND_D1: CN9.81 U11.J4 | length 53
  Top Layer w0.1: v1(58.172,156.388) 58.177,156.383 59.569,156.383 59.702,156.25 CN9.81@61.13,156.25 ; U11.J4@100.275,165.975 100.675,166.375 101.455,166.375 v1(101.775,166.695)
  Bottom Layer w0.1: v1(58.172,156.388) 58.172,156.981 61.097,159.906 92.306,159.906 96.171,163.771 98.071,163.771 100.995,166.695 v1(101.775,166.695)
NAND_D2: CN10.29 U11.K4 | length 36.9
  Top Layer w0.1: U11.K4@100.275,166.775 100.275,168.293 100.467,168.485 v1(100.467,168.561) ; v1(127.051,176.696) 128.274,175.473 128.629,175.473 129.852,174.25 CN10.29@131.13,174.25
  Bottom Layer w0.1: v1(100.467,168.561) 104.812,168.561 112.947,176.696 v1(127.051,176.696)
NAND_D3: CN10.27 U11.K5 | length 38.3
  Top Layer w0.1: U11.K5@99.475,166.775 99.475,168.743 v1(99.486,168.753) ; v1@127.974,176.836 129.265,175.545 129.265,175.226 129.741,174.75 CN10.27@131.13,174.75
  Bottom Layer w0.1: v1(99.486,168.753) 99.864,169.132 104.85,169.132 112.89,177.172 127.615,177.172 v1(127.965,176.823)
NAND_D4: CN9.91 U11.K6 | length 60.7
  Top Layer w0.1: v1(56.647,153.779) 56.676,153.75 CN9.91@61.13,153.75 ; U11.K6@98.675,166.775 98.675,169.922 v1(99.149,170.396)
  Bottom Layer w0.1: v1(56.647,153.779) 56.238,154.189 56.238,157.839 60.76,162.361 88.405,162.361 96.439,170.396 v1(99.149,170.396)
NAND_D5: CN9.95 U11.J7 | length 53.3
  Top Layer w0.1: v1(58.101,152.782) 58.11,152.773 61.107,152.773 CN9.95@61.13,152.75 ; v1(95.966,166.838) 96.389,166.415 97.435,166.415 U11.J7@97.875,165.975
  Bottom Layer w0.1: v1(58.101,152.782) 58.101,153.631 56.941,154.791 56.941,157.387 60.998,161.444 89.892,161.444 95.287,166.838 v1(95.966,166.838)
NAND_D6: CN9.93 U11.K7 | length 56
  Top Layer w0.1: v1(57.188,153.047) 57.566,153.047 57.77,153.25 CN9.93@61.13,153.25 ; v1(97.476,168.377) 97.476,167.174 U11.K7@97.875,166.775
  Bottom Layer w0.1: v1(57.188,153.047) 57.226,153.084 57.226,153.965 56.593,154.598 56.593,157.62 60.868,161.895 88.595,161.895 95.077,168.377 v1(97.476,168.377)
NAND_D7: CN9.99 U11.J8 | length 52.2
  Top Layer w0.1: v1@58.314,151.743 v1(58.551,151.743) 58.558,151.75 CN9.99@61.13,151.75 ; v1(95.005,165.92) 95.061,165.975 U11.J8@97.075,165.975
  Bottom Layer w0.1: v1(58.551,151.743) 58.551,153.646 57.319,154.878 57.319,157.19 61.042,160.913 89.999,160.913 v1(95.005,165.92)
NAND_NCE: CN9.97 R84.1 U11.C6 | length 48.3
  Top Layer w0.1: v1(59.456,152.263) 61.028,152.263 61.072,152.308 CN9.97@61.13,152.25 ; v1(97.541,157.914) 98.006,157.45 R84.1@98.675,157.45 98.675,158.766 99.116,159.207 99.116,159.833 98.982,159.967 98.675,160.275 U11.C6@98.675,161.175
  Bottom Layer w0.1: v1(59.456,152.263) 61.618,154.425 61.888,154.425 65.349,157.886 v1@97.541,157.886 ; v1(97.541,157.914) v1@97.541,157.886 ; v1@97.541,157.886 97.541,157.672 97.755,157.886 v1@97.541,157.886
NAND_NOE: CN10.30 U11.D4 | length 45.6
  Top Layer w0.1: U11.D4@100.275,161.975 100.675,162.375 101.82,162.375 v1(102.183,162.738) ; CN10.30@136.87,174.25 136.878,174.242 136.919,174.283 136.921,174.281 v1(138.579,174.281)
  Bottom Layer w0.1: v1(102.183,162.738) 114.344,174.899 137.22,174.899 137.838,174.281 v1(138.579,174.281)
NAND_NWAIT: CN10.24 U11.C8 | length 52.8
  Top Layer w0.1: U11.C8@97.075,161.175 v1(97.777,160.473) ; CN10.24@136.87,175.75 136.953,175.833 138.844,175.833 139.112,176.1 v1(139.677,176.1)
  Bottom Layer w0.1: v1(97.777,160.473) 101.3,163.996 102.456,163.996 113.879,175.419 137.401,175.419 137.887,174.933 138.7,174.933 139.07,175.303 139.07,175.489 139.299,175.718 139.299,175.723 v1(139.677,176.1)
NAND_NWE: CN10.28 U11.C7 | length 53.2
  Top Layer w0.1: U11.C7@97.875,161.175 98.278,160.772 98.278,159.922 v1(98.6,159.6) ; CN10.28@136.87,174.75 138.829,174.75 139.036,174.957 v1(139.598,174.957)
  Bottom Layer w0.1: v1(98.6,159.6) 98.6,160.749 101.431,163.58 102.533,163.58 114.102,175.149 137.388,175.149 137.804,174.733 138.764,174.733 138.769,174.727 138.923,174.727 139.147,174.951 139.47,174.951 139.537,175.018 139.564,175.045 139.598,175.011 v1(139.598,174.957)
NetB1_1: B1.1 C72.2 R103.2 | length 160.2
  Top Layer w0.1: v1(60.988,112.086) 60.968,112.066 60.968,83.686 110.583,34.07 110.778,33.875 110.778,4.337 108.381,1.941 103.555,1.941 101.56,3.936 101.56,6.045 B1.1@101.823,6.308 ; v1(75.538,114.757) 76.323,113.973 76.323,113.627 76.5,113.45 R103.2@77.4,113.45
  Bottom Layer w0.1: v1(60.988,112.086) 71.532,112.086 74.203,114.757 v1(75.538,114.757)
NetB1_2: B1.2 R101.1 R105.1 | length 163.9
  Top Layer w0.1: v1(61.334,114.673) 61.334,113.636 61.35,113.62 60.374,112.645 60.374,83.459 110.462,33.371 110.462,4.468 110.147,4.152 108.208,2.214 103.812,2.214 102.543,3.483 102.543,5.072 B1.2@102.773,5.301 ; v1(78.541,115.294) 79.485,114.35 R101.1@79.6,114.35 R105.1@79.6,113.45
  Bottom Layer w0.1: v1(61.334,114.673) 71.411,114.673 73.838,117.099 76.732,117.099 v1@78.515,115.316
NetB1_3: B1.3 C71.2 R104.2 | length 159.9
  Top Layer w0.1: v1(60.443,113.696) 60.443,113.714 59.866,113.136 59.866,83.198 108.116,34.948 ; v1(76.836,116.071) 76.836,116.022 78.5,114.358 R104.2@78.5,113.45 ; B1.3@103.777,4.279 103.562,4.064 103.562,2.958 104.023,2.497 108.068,2.497 110.139,4.567 110.139,32.924 108.115,34.947
  Bottom Layer w0.1: v1(60.443,113.696) 71.777,113.696 74.112,116.03 76.801,116.03 v1@76.831,116.06
NetB1_4: B1.4 C93.2 R123.2 | length 125.3
  Top Layer w0.1: v1@58.501,96.509 58.501,93.316 58.501,81.699 98.514,41.686 ; v1(75.278,96.447) 75.278,96.462 75.722,96.906 75.722,98.335 R123.2@75.76,98.373 ; 98.514,41.686 107.115,33.085 107.115,11.595 B1.4@106.202,10.682
  Bottom Layer w0.1: v1(58.502,96.51) 75.212,96.51 v1@75.299,96.423
NetB1_5: B1.5 R138.2 | length 2.2
  Top Layer w0.3: B1.5@107.317,9.733 108.426,10.842 R138.2@108.426,11.436
NetB1_6: B1.6 C92.2 R122.2 | length 128.4
  Top Layer w0.1: v1@59.145,99.346 59.145,82.099 59.936,81.308 109.701,31.544 109.701,31.346 109.701,10.221 B1.6@108.182,8.702 ; v1@73.215,99.37 73.7,98.885 C92.2@73.7,98.378 ; C92.2@73.705,98.373 R122.2@74.66,98.373
  Bottom Layer w0.1: v1@59.134,99.384 v1(73.188,99.384)
  other v1: 59.145,99.388
NetB2_1: B2.1 B2.2 C119.2 R139.2 SB62.2 | length 174
  Top Layer w0.1: 37.064,128.822 37.08,128.838 43.073,128.838 46.796,125.114 51.256,125.114 56.852,119.518 56.852,80.847 96.549,41.15 96.549,12.349 93.95,9.75 B2.2@83.75,9.75
  Top Layer w0.3: B2.1@74.25,9.75 R139.2@74.25,11.425 C119.2@83.75,11.425 B2.2@83.75,9.75
NetC1_2: C1.2 C2.2 C6.2 C7.2 JP4.2 R3.2 R8.2 U1.1 U2.1 U3.1 U4.1 | length 59.9
  Top Layer w0.127: v1(56.419,243.432) C6.2@56.419,242.642 ; R8.2@56.448,240.085 56.388,240.085 55.578,240.895 55.578,242.41 55.81,242.642 C6.2@56.419,242.642 ; U3.1@58.438,241.579 58.438,241.866 57.662,242.642 C6.2@56.419,242.642 ; U1.1@59.338,246.325 59.338,246.09 60.081,245.346 C1.2@61.3,245.346 61.3,244.616 v1(61.276,244.592) ; v1(63.6,243.078) C7.2@63.6,242.3 63.633,242.333 65.077,242.333 65.55,241.86 U4.1@65.55,241.579 ; U2.1@66.45,246.325 66.45,246.05 67.15,245.35 C2.2@67.15,244.1 67.172,244.122 v1(68.427,244.122) 68.427,245.302 R3.2@68.475,245.35
  Bottom Layer w0.127: 63.56,244.592 63.6,244.552 ; v1@68.378,244.122 v1(68.427,244.122)
  Bottom Layer w0.4: v1(56.419,243.432) 58.265,245.278 60.591,245.278 v1(61.276,244.592) 63.56,244.592 64.062,245.095 67.405,245.095 v1@68.378,244.122 ; v1(63.6,243.078) 63.6,244.552 ; v1(68.427,244.122) 68.427,236.634 75.272,229.789 75.272,227.338 74.005,226.071 72.246,226.071 71.224,225.049 JP4.2@71.224,223.607
NetC4_1: C4.1 U5.8 | length 1.8
  Top Layer w0.1: U5.8@156.865,240.315 156.865,242.115 C4.1@156.875,242.125
NetC5_1: C5.1 U5.5 | length 1.8
  Top Layer w0.1: U5.5@160.675,240.315 C5.1@160.675,242.125
NetC5_2: C5.2 U5.7 | length 6.9
  Top Layer w0.1: U5.7@158.135,240.315 158.135,239.715 158.791,239.06 159.848,239.06 160.043,239.254 160.043,242.469 160.599,243.025 C5.2@160.675,243.025
NetC9_1: C9.1 CN2.4 | length 1.9
  Top Layer w0.1: C9.1@118,240.625 CN2.4@118,242.5
NetC9_2: C9.2 R9.1 R10.2 | length 1.9
  Top Layer w0.1: R10.2@118,237.825 R9.1@118,238.775 C9.2@118,239.725
NetC10_1: C10.1 CN1.4 R7.2 | length 3
  Top Layer w0.1: C10.1@101,239.5 R7.2@101,240.45 CN1.4@101,242.5
NetC10_2: C10.2 R11.1 | length 0.8
  Top Layer w0.1: R11.1@101,237.775 C10.2@101,238.6
NetC14_1: C14.1 R15.2 R16.1 U6.4 | length 3.5
  Top Layer w0.1: R15.2@98.95,233.95 U6.4@100.35,233.95 C14.1@100.35,232.875 R16.1@99.35,232.875
NetC14_2: C14.2 R18.1 | length 0.8
  Top Layer w0.1: R18.1@100.35,231.15 C14.2@100.35,231.975
NetC16_1: C16.1 CN23.C1 U5.17 | length 10
  Top Layer w0.1: v1(148.076,226.251) 148.076,226.288 151.089,229.3 C16.1@151.775,229.3 151.775,231.125 U5.17@151.785,231.135
  Bottom Layer w0.1: v1(148.076,226.251) 148.08,226.248 CN23.C1@148.08,223.03
NetC19_1: C19.1 U8.E6 | length 6.1
  Top Layer w0.1: C19.1@83.514,221.743 84.264,221.743 v1(84.27,221.738)
  Top Layer w0.2: U8.E6@84,216.825 v3(84.16,216.985)
  Bottom Layer w0.1: v3@84.15,216.975 83.85,217.275 83.85,219.073 84.353,219.576 84.353,221.222 84.27,221.305 v1(84.27,221.738)
NetC21_1: C21.1 U8.D7 | length 5.5
  Top Layer w0.1: C21.1@79.942,221.065 79.942,220.346 v1(79.961,220.327)
  Top Layer w0.2: v3(83.34,217.485) U8.D7@83.5,217.325
  Bottom Layer w0.1: v1(79.961,220.327) 82.218,218.07 82.755,218.07 v3(83.34,217.485)
NetC21_2: C21.2 SB3.2 | length 1.3
  Top Layer w0.1: SB3.2@78.608,221.965 C21.2@79.942,221.965
NetC22_1: C22.1 U8.H8 | length 2.5
  Top Layer w0.1: U8.H8@85.5,217.825 86.098,218.423 86.098,219.796 86.177,219.875 C22.1@86.35,219.875
NetC22_2: C22.2 U8.G8 | length 5.7
  Top Layer w0.1: C22.2@86.35,221.275 86.457,221.382 v1(87.346,221.382)
  Top Layer w0.2: U8.G8@85,217.825 v3(85.16,217.985)
  Bottom Layer w0.1: v3(85.16,217.985) 85.17,217.975 85.382,217.975 87.346,219.939 v1(87.346,221.382)
NetC23_2: C23.2 U8.C9 | length 2.6
  Top Layer w0.18: C23.2@81.125,220.125 81.2,220.125 U8.C9@83,218.325
NetC24_2: C24.2 U8.D9 | length 2.4
  Top Layer w0.18: C24.2@82.05,220.125 82.14,220.035 82.14,219.685 U8.D9@83.5,218.325
NetC26_1: C26.1 U8.H7 | length 4
  Top Layer w0.1: U8.H7@85.5,217.325 86.365,218.19 86.365,218.796 87.114,219.546 87.114,219.687 87.675,220.248 C26.1@87.675,220.375
NetC28_1: C28.1 U8.G7 | length 3.4
  Top Layer w0.1: v1(86.844,218.539) 87.301,218.539 87.673,218.911 C28.1@87.673,218.996
  Top Layer w0.2: U8.G7@85,217.325 v3(85.16,217.485)
  Bottom Layer w0.1: v3(85.16,217.485) 85.17,217.475 85.781,217.475 v1(86.844,218.539)
NetC31_2: C31.2 JP4.3 U8.A7 | length 15.9
  Top Layer w0.1: JP4.3@68.684,223.607 71.482,220.81 75.129,220.81 76.913,219.026 79.5,219.026 80.025,218.501 C31.2@80.025,218.45 81.15,217.325 U8.A7@82,217.325
NetC34_1: C34.1 R36.2 | length 0.8
  Top Layer w0.2: C34.1@88.5,217.475 R36.2@89.3,217.475
NetC34_2: C34.2 CN5.6 U8.H6 | length 29.7
  Top Layer w0.2: U8.H6@85.5,216.825 86.15,217.475 C34.2@87.6,217.475 87.6,217.91 87.82,218.129 90.086,218.129
  Top Layer w0.23: 90.086,218.129 90.825,218.868
  Top Layer w0.3: CN5.6@83.811,236.635 84.113,236.635 85.668,235.08 89.876,235.08 90.825,234.132 90.825,218.868
NetC35_2: C35.2 R35.1 U8.B6 | length 3.5
  Top Layer w0.1: R35.1@80.025,217.475 80.037,217.463 80.037,216.634 v1(80.679,216.634)
  Top Layer w0.2: v3(82.34,216.985) U8.B6@82.5,216.825
  Bottom Layer w0.1: v1(80.679,216.634) 81.145,216.634 81.497,216.985 v3(82.34,216.985)
NetC36_1: C36.1 R37.2 | length 0.8
  Top Layer w0.2: C36.1@88.5,216.425 R37.2@89.3,216.425
NetC36_2: C36.2 CN5.4 U8.G6 | length 36
  Top Layer w0.127: C36.2@87.583,216.425 87.591,216.434 C36.2@87.6,216.425
  Top Layer w0.2: U8.G6@85,216.825 v3(85.16,216.985) ; v1(86.625,216.975) 87.034,216.975 C36.2@87.583,216.425 ; C36.2@87.6,216.425 87.6,215.989 87.836,215.753 91.176,215.753 91.828,216.404
  Top Layer w0.3: CN5.4@90.711,244.035 90.711,238.798 91.828,237.681 91.828,216.404
  Bottom Layer w0.1: v3(85.16,216.985) v3@85.17,216.975
  Bottom Layer w0.2: v3@85.17,216.975 v1(86.625,216.975)
NetC38_1: C38.1 R41.2 R42.1 | length 2
  Top Layer w0.127: R42.1@75.554,214.313 R42.1@75.679,214.188 ; R41.2@76.504,214.188 R41.2@76.554,214.238
  Top Layer w0.2: R42.1@75.679,214.188 R41.2@76.504,214.188 ; R41.2@76.554,214.238 C38.1@77.454,214.238
NetC38_2: C38.2 U8.B3 | length 4.7
  Top Layer w0.1: C38.2@78.354,214.238 C38.2@78.36,214.232
  Top Layer w0.2: C38.2@78.36,214.232 v1(79.053,214.232) ; v3(82.34,215.485) U8.B3@82.5,215.325
  Bottom Layer w0.1: 81.182,215.166 81.491,215.475 82.052,215.475 v3@82.34,215.475
  Bottom Layer w0.2: v1(79.053,214.232) 79.973,214.232 80.248,214.232 81.182,215.166
NetC39_1: C39.1 R46.1 R47.1 | length 1.8
  Top Layer w0.1: R46.1@75.554,213.238 R46.1@75.679,213.363 ; R47.1@76.704,213.388 R47.1@76.721,213.37 ; C39.1@77.396,213.37 C39.1@77.454,213.313
  Top Layer w0.2: R46.1@75.679,213.363 R47.1@76.504,213.363 ; R47.1@76.721,213.37 C39.1@77.396,213.37
NetC39_2: C39.2 U8.A2 | length 4.3
  Top Layer w0.1: U8.A2@81.977,214.825 U8.A2@82,214.825
  Top Layer w0.2: C39.2@78.354,213.313 78.879,213.313 80.083,214.517 81.669,214.517 U8.A2@81.977,214.825
NetC44_2: C44.2 U8.F1 | length 2
  Top Layer w0.1: U8.F1@84.5,214.325 84.5,213.475 84.65,213.325 C44.2@84.65,212.425
NetC45_2: C45.2 U9.62 X1.3 | length 5.4
  Top Layer w0.1: U9.62@25.075,211.025 28.435,211.025 C45.2@28.533,211.123 28.604,211.052 29.447,211.052 29.85,211.455 X1.3@29.85,211.6 X1.3@29.85,211.8
NetC46_2: C46.2 R53.1 X1.1 | length 4.3
  Top Layer w0.1: R53.1@27.639,210.321 28.531,210.321 C46.2@28.533,210.323 30.654,210.323 31.45,209.527 X1.1@31.45,209.4
NetC52_1: C52.1 C53.2 CN11.48 L4.1 | length 7
  Top Layer w0.1: L4.1@190.446,174.958 190.579,174.825 C52.1@192.6,174.825 ; C52.1@192.729,174.83 192.729,174.873 193.462,175.606 194.544,175.606 C53.2@194.6,175.55 ; C53.2@194.692,175.598 194.729,175.561 195.086,175.561 195.275,175.75 CN11.48@197.13,175.75
NetC52_2: C52.2 C53.1 CN11.50 L3.1 | length 6.9
  Top Layer w0.1: L3.1@190.614,177.153 190.636,177.175 C52.2@192.6,177.175 ; C52.2@192.759,177.251 192.759,177.065 193.441,176.382 194.532,176.382 C53.1@194.6,176.45 ; C53.1@194.605,176.452 194.62,176.437 195.43,176.437 195.616,176.25 CN11.50@197.13,176.25
NetC59_2: C59.2 SB25.1 | length 1.5
  Top Layer w0.13: C59.2@123.262,160.508 124.168,160.508 SB25.1@124.615,160.061
NetC61_2: C61.2 U12.27 | length 3.9
  Top Layer w0.1: C61.2@25.282,155.973 25.282,153.49 25.497,153.275 U12.27@26.65,153.275
NetC62_1: C62.1 U12.2 | length 2.1
  Top Layer w0.1: C62.1@17.725,153.2 17.8,153.275 U12.2@19.75,153.275
NetC62_2: C62.2 U12.1 | length 2.1
  Top Layer w0.1: C62.2@17.725,154.1 17.9,153.925 U12.1@19.75,153.925
NetC63_1: C63.1 U12.28 | length 2.5
  Top Layer w0.1: U12.28@26.65,153.925 28.015,153.925 C63.1@28.838,153.102
NetC63_2: C63.2 U12.24 | length 2.8
  Top Layer w0.1: U12.24@26.65,151.325 28.436,151.325 28.736,151.625 28.736,152.1 C63.2@28.838,152.202
NetC64_2: C64.2 U12.3 | length 2.1
  Top Layer w0.1: C64.2@17.775,152.275 18.344,152.275 18.694,152.625 U12.3@19.75,152.625
NetC69_1: C69.1 CN16.1 L5.2 Z5.1 | length 6.9
  Top Layer w0.1: L5.2@7.274,122.143 L5.2@7.279,122.139
  Top Layer w0.4: CN16.1@4.125,123.7 5.133,123.7 v1@5.543,123.289
  Top Layer w0.6: v1@5.543,123.289 v1(5.549,123.284) 6.689,122.143 L5.2@7.274,122.143 ; C69.1@7.279,120.255 L5.2@7.279,122.139
  Bottom Layer w0.25: v1(5.549,123.284) 5.549,123.774 5.696,123.922 6.24,123.922
NetC74_2: C74.2 R105.2 U20.18 | length 3.2
  Top Layer w0.1: U20.18@78.35,109.85 78.35,110.4 79.55,111.6 C74.2@79.55,111.7 79.55,112.5 R105.2@79.6,112.55
NetC76_1: C76.1 C87.2 CN18.T1 U21.7 Z1.1 | length 18.3
  Top Layer w0.1: v1(43.779,103.159) v1@43.799,103.159
  Top Layer w0.25: 17.9,102.877 18.353,102.424 Z1.1@18.892,102.424 ; 19.132,102.574 19.132,103.232 19.823,103.923 v1@20.492,103.923
  Top Layer w0.3: v1(20.506,103.925) 20.512,103.931 C87.2@21.145,103.931
  Top Layer w0.5: v1@20.494,103.919 20.494,105.054 C76.1@21.17,105.731 21.528,105.373 v1(23.278,105.373)
  Top Layer w0.6: v1@43.799,103.159 v1(44.392,103.752) U21.7@45.74,103.752
  Top Layer w1: CN18.T1@15.641,103.337 17.439,103.337 17.9,102.877
  Bottom Layer w1: CN18.T1@15.63,103.35 19.919,103.35 v1@20.507,103.938
NetC79_2: C79.2 C82.2 L6.2 U20.9 | length 7.5
  Top Layer w0.1: U20.9@82.35,106.85 84.875,106.85 C82.2@84.9,106.875 86.15,106.875 86.7,107.425 ; C79.2@86.7,108.15 86.7,107.425 ; L6.2@88.9,107.4 88.875,107.425 86.7,107.425
NetC80_2: C80.2 R110.1 X3.2 | length 4
  Top Layer w0.1: X3.2@30.82,110.902 30.82,110.576 32.084,109.312 C80.2@32.084,108.414 32.084,107.573 R110.1@32.012,107.502
NetC81_2: C81.2 R111.1 X3.1 | length 4.1
  Top Layer w0.1: R111.1@33.063,107.502 32.958,107.606 32.958,108.393 C81.2@32.979,108.414 32.979,109.055 34.52,110.596 X3.1@34.52,110.902
NetC83_2: C83.2 U22.34 | length 2
  Top Layer w0.1: C83.2@30.954,105.896 30.954,105.916 31.825,105.045 U22.34@31.825,104.3
NetC85_2: C85.2 SB64.2 U22.26 | length 7.7
  Top Layer w0.1: U22.26@35.575,103.05 36.125,103.05 36.55,103.475 36.55,106.225 36.7,106.375 C85.2@37.35,106.375 ; C85.2@37.375,106.35 37.375,106.75 37.8,107.175 SB64.2@39.7,107.175
NetC86_2: C86.2 D1.1 R113.2 U20.7 | length 4.1
  Top Layer w0.1: U20.7@82.35,105.85 C86.2@83.8,105.85 R113.2@84.825,105.85 85.349,105.85 85.899,105.3 D1.1@86.18,105.3
NetC95_2: C95.2 U22.14 | length 1.4
  Top Layer w0.1: C95.2@32.825,97.435 U22.14@32.825,98.8
NetC98_2: C98.2 C101.1 CN19.27 CN19.29 L8.2 | length 9.1
  Top Layer w0.3: C98.2@119.05,95.075 L8.2@119.05,97.176 ; C98.2@119.052,94.995 119.775,94.273 C101.1@119.775,93.075 ; CN19.29@119.25,90.87 119.25,92.97 119.363,93.084 C101.1@119.754,93.084 ; C101.1@119.743,93.04 119.75,93.033 CN19.27@119.75,90.87
NetC99_2: C99.2 C100.1 CN18.B1 U21.6 Z2.1 | length 9.5
  Top Layer w0.1: v1@47.059,105 v1(47.059,105.022) ; v1@47.539,104.542 47.626,104.455 v1(47.626,104.433)
  Top Layer w0.2: v1(18.654,99.133) 19.066,98.721 19.066,98.349 Z2.1@18.892,98.349
  Top Layer w0.3: v1(17.843,98.763) 18.213,99.133 v1(18.654,99.133) ; v1(20.353,95.569) 20.357,95.569 20.359,95.571 C99.2@21.175,95.571
  Top Layer w0.5: v1(18.977,93.769) 18.98,93.766 C100.1@21.138,93.766 ; v1@20.357,95.569 20.357,94.547 C100.1@21.138,93.766 ; C100.1@21.17,93.766 C100.1@21.138,93.766
  Top Layer w0.6: U21.6@45.74,105.022 v1(47.059,105.022) ; v1@47.059,105 v1(47.626,104.433)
